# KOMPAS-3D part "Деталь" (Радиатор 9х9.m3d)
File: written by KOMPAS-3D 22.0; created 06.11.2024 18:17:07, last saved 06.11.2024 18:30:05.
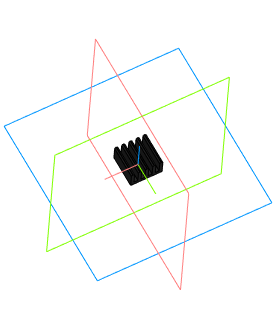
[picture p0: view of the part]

Document properties: Автор: Andrey; Полное имя файла: C:\Users\User1\Downloads\Telegram Desktop\3D\3D\Радиатор 9х9.m3d

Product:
- Part/product: Деталь
    Масса: 0.001885

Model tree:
1. Эскиз:1
2. Элемент выдавливания:1
     Расстояние 1 = 5
3. Эскиз:2  (with: Элемент выдавливания:1)
4. Элемент выдавливания:2
     Расстояние 2 = 4
5. Скругление:1  (with: Элемент выдавливания:2, Элемент выдавливания:1)
     Радиус = 0.4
